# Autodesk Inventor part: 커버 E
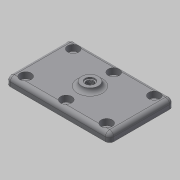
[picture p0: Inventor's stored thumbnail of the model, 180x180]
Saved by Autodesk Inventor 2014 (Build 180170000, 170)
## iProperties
Created: 2020-04
Part Number: 커버 E
Material: 알루미늄 6061
Document SubType Name: Modeling
Designer: mduedu
Density: 1 g/cm^3
Appearance: 기본값
Author: mduedu
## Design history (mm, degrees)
sketch "스케치1"
  geometry: L1 (37, 23)-(-37, 23); L2 (-37, 23)-(-37, -23); L3 (-37, -23)-(37, -23); L4 (37, -23)-(37, 23); L5 (37, 23)-(-37, -23); L6 (-37, 23)-(37, -23); 1 further point
  constraints: 12 end point, 2 midpoint, 2 parallel, 1 horizontal, 1 perpendicular
  dimensions: "d0" = 74 distance of L3.end L2.end; "d1" = 46 distance of L2.end L1.end
extrude "돌출1" new body sketch "스케치1" distance "d2" = 6; taper "d3" = 0 deg
sketch "스케치2"
  geometry: C1 r 6 at (0, 0); 1 further point
  constraints: 1 centre point, 1 coincident
  dimensions: "d4" = 12 diameter of C1
extrude "돌출2" join sketch "스케치2" distance "d5" = 3; taper "d6" = 0 deg
fillet "모깎기1" dims "d7" = 3
fillet "모깎기2" dims "d8" = 3
fillet "모깎기3" dims "d9" = 3
sketch "스케치3"
  geometry: L1 (-30, -13)-(30, -13); L2 (30, -13)-(30, 13); L3 (30, 13)-(-30, 13); L4 (-30, 13)-(-30, -13); L5 (-30, -13)-(30, 13); L6 (30, -13)-(-30, 13); 1 further point
  constraints: 12 end point, 2 midpoint, 2 parallel, 1 horizontal, 1 perpendicular
  dimensions: "d10" = 60 distance of L3.end L2.end; "d11" = 26 distance of L2.end L1.end
extrude "돌출3" join sketch "스케치3" distance "d12" = 2; taper "d13" = 0 deg
fillet "모깎기4" dims "d14" = 3
chamfer "모따기1" distance "d15" = 0.5; stored, may be unused: second distance "d16" = 2, angle "d17" = 45 deg
sketch "스케치4"
  geometry: L1 (-29, -17)-(29, -17); L2 (29, -17)-(29, 17); L3 (29, 17)-(-29, 17); L4 (-29, 17)-(-29, -17); L5 (-29, -17)-(29, 17); L6 (29, -17)-(-29, 17); 7 further points
  constraints: 12 end point, 4 coincident, 4 midpoint, 2 parallel, 1 horizontal, 1 perpendicular
  dimensions: "d18" = 58 distance of L3.end L2.end; "d19" = 34 distance of L2.end L1.end
hole "구멍1" sketch "스케치4" at (-29, 17), (-29, -17), (29, -17), (29, 17), (0, 17), (0, -17) diameter "d20" = 4.5; stored, may be unused: countersink angle "d24" = 90 deg, drill point angle "d26" = 118 deg; dims "d21" = 6, "d22" = 8, "d23" = 4.4, "d25" = 8
hole "구멍2" diameter "d29" = 5.188; stored, may be unused: countersink angle "d33" = 90 deg, drill point angle "d35" = 118 deg; dims "d27" = 10, "d28" = 10, "d30" = 6, "d31" = 8, "d32" = 4.4, "d34" = 8
sketch "스케치5"
  geometry: C1 r 3.5 at (0, 0); 1 further point
  constraints: 1 centre point, 1 coincident
  dimensions: "d36" = 7 diameter of C1
extrude "돌출4" cut sketch "스케치5" distance "d37" = 1; taper "d38" = 0 deg
node "솔리드1"
